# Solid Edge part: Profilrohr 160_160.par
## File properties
Username: ahadarics
Dokumentum tartalom típus: 0
Author: ahadarics
Last saved by: ahadarics
Revision: 84
Sűrűség: 0,000 kg/m^3
Pontosság: 0,990
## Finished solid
Body 1: solid body, 6 faces, 9 edges, 5 vertices.
  Faces by surface: cone 2, cylinder 2, plane 2
  Edges by curve: circle 6, line 3
Bounding box of the edges (mm): 167.000 x 167.000 x 240.000, from (-83.5, -83.5, -187.5) to (83.5, 83.5, 52.5).
Cylindrical faces by radius (mm): R80 x1, R83.5 x1
Conical faces (half-angle, radius in mm at the cone's reference point): 45 deg R80.25 x2
Planar faces by outward normal: +z 1, -z 1
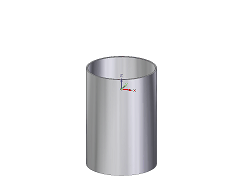
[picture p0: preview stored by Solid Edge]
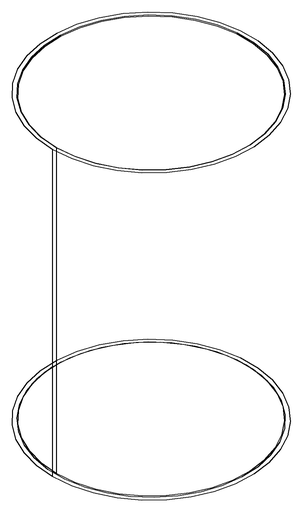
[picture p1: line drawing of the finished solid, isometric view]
